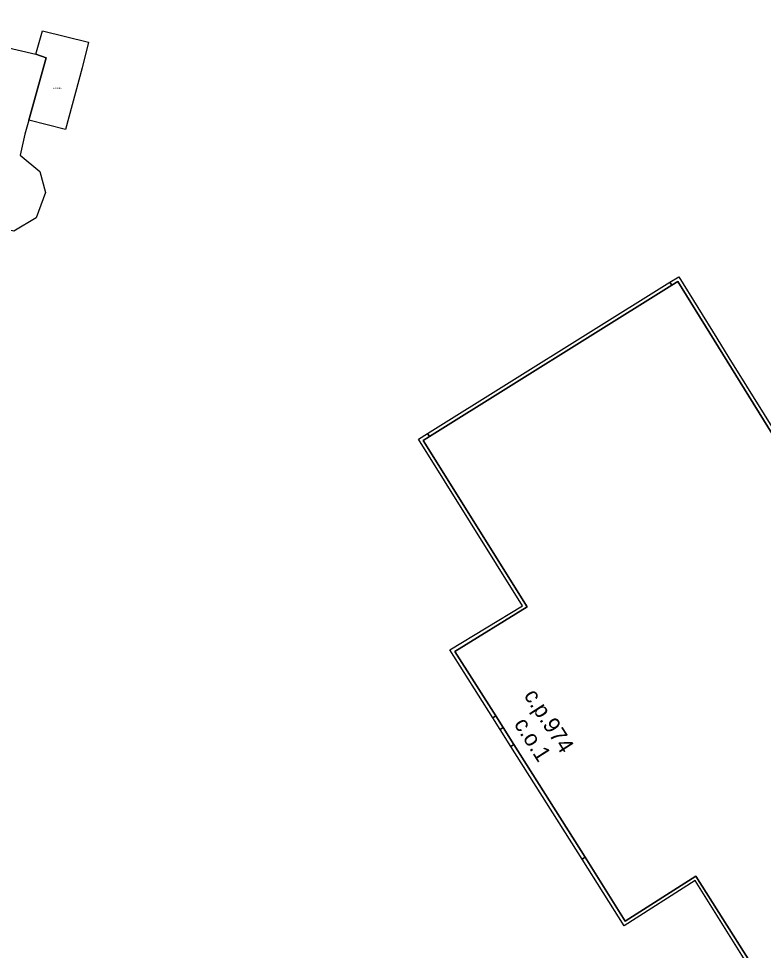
# Model space of a CAD drawing. Extents: x -600391 to -599491, y -1160176 to -1159402.
# Drawn here: x -599855.3 to -599808.9, y -1159510.4 to -1159452.4 of the extents above; entities that cross this region are included whole.
import ezdxf

# ---------------------------------------------------------------- set-up
doc = ezdxf.new("R2010")
doc.units = 0
for name, color, linetype in [('Level 10', 7, 'Continuous'), ('Level 12', 7, 'Continuous'), ('Level 24', 7, 'Continuous'), ('Level 61', 7, 'Continuous'), ('Level 62', 7, 'Continuous')]:
    doc.layers.add(name, color=color, linetype=linetype)

msp = doc.modelspace()

# ---------------------------------------------------------------- linework, layer by layer
at = {"layer": 'Level 61'}
for points in [[(-599854.18, -1159454.6), (-599853.77, -1159453.15)], [(-599853.77, -1159453.15), (-599850.9, -1159453.85)], [(-599856.24, -1159454.11), (-599854.18, -1159454.6)], [(-599850.9, -1159453.85), (-599851.3, -1159455.44)], [(-599853.53, -1159454.83), (-599854.62, -1159458.7)], [(-599854.62, -1159458.7), (-599853.53, -1159454.83)], [(-599854.18, -1159454.6), (-599853.53, -1159454.83)], [(-599853.53, -1159454.83), (-599854.18, -1159454.6)], [(-599851.3, -1159455.44), (-599852.34, -1159459.29)], [(-599854.62, -1159458.7), (-599854.87, -1159459.57)], [(-599852.34, -1159459.29), (-599854.62, -1159458.7)], [(-599854.87, -1159459.57), (-599855.16, -1159460.88)], [(-599855.16, -1159460.88), (-599853.94, -1159461.91)], [(-599853.94, -1159461.91), (-599853.58, -1159463.2)], [(-599853.58, -1159463.2), (-599854.16, -1159464.78)], [(-599854.16, -1159464.78), (-599855.56, -1159465.62)], [(-599829.78, -1159478.22), (-599814.68, -1159468.79)], [(-599814.68, -1159468.79), (-599814.12, -1159468.47)], [(-599814.56, -1159468.98), (-599814.68, -1159468.79)], [(-599814.68, -1159468.79), (-599814.56, -1159468.98)], [(-599814.19, -1159468.75), (-599814.56, -1159468.98)], [(-599814.56, -1159468.98), (-599814.19, -1159468.75)], [(-599807.77, -1159479.12), (-599814.19, -1159468.75)], [(-599814.19, -1159468.75), (-599807.77, -1159479.12)], [(-599814.12, -1159468.47), (-599811.76, -1159472.28)], [(-599829.66, -1159478.41), (-599814.56, -1159468.98)], [(-599814.56, -1159468.98), (-599829.66, -1159478.41)], [(-599811.76, -1159472.28), (-599811, -1159473.5)], [(-599811, -1159473.5), (-599807.71, -1159478.8)], [(-599830.34, -1159478.57), (-599829.78, -1159478.22)], [(-599823.87, -1159488.95), (-599830.34, -1159478.57)], [(-599830.05, -1159478.65), (-599829.66, -1159478.41)], [(-599829.66, -1159478.41), (-599830.05, -1159478.65)], [(-599823.57, -1159489.01), (-599830.05, -1159478.65)], [(-599830.05, -1159478.65), (-599823.57, -1159489.01)], [(-599829.78, -1159478.22), (-599829.66, -1159478.41)], [(-599829.66, -1159478.41), (-599829.78, -1159478.22)], [(-599828.39, -1159491.7), (-599823.87, -1159488.95)], [(-599828.07, -1159491.79), (-599823.57, -1159489.01)], [(-599823.57, -1159489.01), (-599828.07, -1159491.79)], [(-599825.72, -1159495.93), (-599828.39, -1159491.7)], [(-599825.53, -1159495.81), (-599828.07, -1159491.79)], [(-599828.07, -1159491.79), (-599825.53, -1159495.81)], [(-599825.53, -1159495.81), (-599825.72, -1159495.93)], [(-599825.72, -1159495.93), (-599825.53, -1159495.81)], [(-599825.26, -1159496.66), (-599825.72, -1159495.93)], [(-599825.07, -1159496.53), (-599825.53, -1159495.81)], [(-599825.53, -1159495.81), (-599825.07, -1159496.53)], [(-599825.26, -1159496.66), (-599825.07, -1159496.53)], [(-599825.07, -1159496.53), (-599825.26, -1159496.66)], [(-599824.59, -1159497.71), (-599825.26, -1159496.66)], [(-599824.4, -1159497.59), (-599825.07, -1159496.53)], [(-599825.07, -1159496.53), (-599824.4, -1159497.59)], [(-599824.59, -1159497.71), (-599824.4, -1159497.59)], [(-599824.4, -1159497.59), (-599824.59, -1159497.71)], [(-599820.15, -1159504.73), (-599824.59, -1159497.71)], [(-599819.96, -1159504.61), (-599824.4, -1159497.59)], [(-599824.4, -1159497.59), (-599819.96, -1159504.61)], [(-599819.96, -1159504.61), (-599820.15, -1159504.73)], [(-599820.15, -1159504.73), (-599819.96, -1159504.61)], [(-599817.53, -1159508.88), (-599820.15, -1159504.73)], [(-599817.46, -1159508.59), (-599819.96, -1159504.61)], [(-599819.96, -1159504.61), (-599817.46, -1159508.59)], [(-599813.06, -1159505.79), (-599817.46, -1159508.59)], [(-599817.46, -1159508.59), (-599813.06, -1159505.79)], [(-599809.71, -1159511.1), (-599813.06, -1159505.79)], [(-599813.06, -1159505.79), (-599809.71, -1159511.1)], [(-599813.11, -1159506.07), (-599817.53, -1159508.88)], [(-599809.89, -1159511.21), (-599813.11, -1159506.07)]]:
    msp.add_lwpolyline(points, dxfattribs=at)
at = {"layer": 'Level 62'}
for points in [[(-599854.62, -1159458.7), (-599854.87, -1159459.57), (-599855.16, -1159460.88), (-599853.94, -1159461.91), (-599853.58, -1159463.2), (-599854.16, -1159464.78), (-599855.56, -1159465.62), (-599856.49, -1159465.4), (-599857, -1159467.51), (-599857.56, -1159469.65), (-599861, -1159468.75), (-599866.19, -1159467.39), (-599866.77, -1159467.26), (-599862.67, -1159452.38), (-599860.51, -1159452.93), (-599857.44, -1159453.77), (-599856.24, -1159454.11), (-599854.18, -1159454.6), (-599853.53, -1159454.83), (-599854.62, -1159458.7)], [(-599853.77, -1159453.15), (-599850.9, -1159453.85), (-599851.3, -1159455.44), (-599852.34, -1159459.29), (-599854.62, -1159458.7), (-599853.53, -1159454.83), (-599854.18, -1159454.6), (-599853.77, -1159453.15)], [(-599809.71, -1159511.1), (-599813.06, -1159505.79), (-599817.46, -1159508.59), (-599819.96, -1159504.61), (-599824.4, -1159497.59), (-599825.07, -1159496.53), (-599825.53, -1159495.81), (-599828.07, -1159491.79), (-599823.57, -1159489.01), (-599830.05, -1159478.65), (-599829.66, -1159478.41), (-599814.56, -1159468.98), (-599814.19, -1159468.75), (-599807.77, -1159479.12), (-599803.39, -1159476.36), (-599800.84, -1159480.34), (-599795.25, -1159489.06), (-599792.68, -1159493.06), (-599797.14, -1159495.85), (-599792.89, -1159502.66), (-599790.35, -1159506.72), (-599789.48, -1159508.11), (-599782.84, -1159518.74)], [(-599829.78, -1159478.22), (-599814.68, -1159468.79), (-599814.56, -1159468.98), (-599829.66, -1159478.41), (-599829.78, -1159478.22)], [(-599811.76, -1159472.28), (-599811, -1159473.5), (-599807.71, -1159478.8), (-599803.31, -1159476.07), (-599800.66, -1159480.22), (-599800.84, -1159480.34), (-599803.39, -1159476.36), (-599807.77, -1159479.12), (-599814.19, -1159468.75), (-599814.56, -1159468.98), (-599814.68, -1159468.79), (-599814.12, -1159468.47), (-599811.76, -1159472.28)], [(-599825.72, -1159495.93), (-599828.39, -1159491.7), (-599823.87, -1159488.95), (-599830.34, -1159478.57), (-599829.78, -1159478.22), (-599829.66, -1159478.41), (-599830.05, -1159478.65), (-599823.57, -1159489.01), (-599828.07, -1159491.79), (-599825.53, -1159495.81), (-599825.72, -1159495.93)], [(-599825.72, -1159495.93), (-599825.53, -1159495.81), (-599825.07, -1159496.53), (-599825.26, -1159496.66), (-599825.72, -1159495.93)], [(-599824.4, -1159497.59), (-599824.59, -1159497.71), (-599825.26, -1159496.66), (-599825.07, -1159496.53), (-599824.4, -1159497.59)], [(-599819.96, -1159504.61), (-599820.15, -1159504.73), (-599824.59, -1159497.71), (-599824.4, -1159497.59), (-599819.96, -1159504.61)], [(-599809.71, -1159511.1), (-599809.89, -1159511.21), (-599813.11, -1159506.07), (-599817.53, -1159508.88), (-599820.15, -1159504.73), (-599819.96, -1159504.61), (-599817.46, -1159508.59), (-599813.06, -1159505.79), (-599809.71, -1159511.1)]]:
    msp.add_lwpolyline(points, dxfattribs=at)

# ---------------------------------------------------------------- texts
at = {"layer": 'Level 10'}
msp.add_text('c.o.1', height=1, rotation=302.69047, dxfattribs=at).set_placement((-599824.431, -1159496.317))
at = {"layer": 'Level 12'}
msp.add_text('c.p.974', height=1, rotation=302.69047, dxfattribs=at).set_placement((-599823.81, -1159494.532))
at = {"layer": 'Level 24'}
msp.add_text('c.z.1745', height=0.1, dxfattribs=at).set_placement((-599853.114, -1159456.757))

doc.saveas('drawing.dxf')
